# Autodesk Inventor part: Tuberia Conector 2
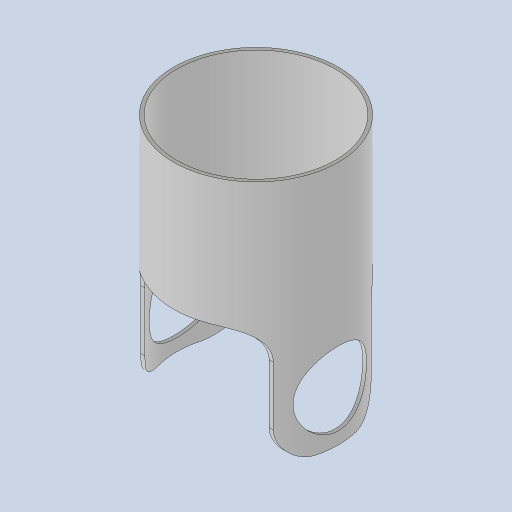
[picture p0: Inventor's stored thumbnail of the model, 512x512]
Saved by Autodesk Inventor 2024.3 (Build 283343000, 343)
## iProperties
Created: 2025-10
Part Number: Tuberia Conector 2
Material: Genérico
Document SubType Name: Modeling
Designer: Asus
Density: 1 g/cm^3
Appearance: Valor por defecto
Author: Asus
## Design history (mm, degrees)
sketch "Boceto1"
  geometry: C1 r 84.138 at (0, 0); C2 r 80.738 at (0, 0); 1 further point
  constraints: 2 centre point, 2 coincident
  dimensions: "d0" = 168.275 diameter of C1; "d1" = 3.4 radial gap between concentric circles of C1 C2
extrude "Extrusión1" new body sketch "Boceto1" distance "d2" = 250; taper "d3" = 0 deg
sketch "Boceto2"
  geometry: L1 (-250, -80.738)-(-250, 80.738) reference; L2 (-250, 84.138)-(-250, -84.138) reference; L3 (-130, 84.138)-(-130, 50); L4 (-130, 50)-(-250, 50); L5 (-250, -50)-(-130, -50); L6 (-130, -50)-(-130, -84.138); L7 (0, 84.138)-(-250, 84.138) reference; L8 (0, -84.138)-(-250, -84.138) reference; L9 (-240, 0)-(40, 0) reference; L10 (-130, 84.138)-(-250, 84.138); L11 (-250, 84.138)-(-250, 50); L12 (-250, 50)-(-130, 50); L13 (-130, 50)-(-130, 84.138); L14 (-250, -50)-(-130, -50); L15 (-130, -50)-(-130, -84.138); L16 (-130, -84.138)-(-250, -84.138); L17 (-250, -84.138)-(-250, -50); 3 further points
  constraints: 24 end point, 5 point on line, 4 parallel, 3 perpendicular, 2 horizontal, 1 vertical
  dimensions: "d4" = 100 distance between parallel lines of L5 L4; "d5" = 50 distance between parallel lines of L9 L4 (= 0.5 x d4); "d6" = 120 distance between parallel lines of L1 L6
extrude "Extrusión2" cut sketch "Boceto2" extent not by distance; stored distance "d7" = 0; taper "d8" = 0 deg
sketch "Boceto3"
  geometry: L1 (-240, 0)-(40, 0) reference; L2 (-250, -50)-(-250, 50) reference; 2 further points
  dimensions: "d9" = 0 distance from line of L1 point (-200, 0); "d10" = 50 distance from line of point (-200, 0) L2
hole "Agujero1" sketch "Boceto3" at (-200, 0) diameter "d11" = 75; stored, may be unused: countersink angle "d15" = 90 deg, drill point angle "d17" = 118 deg; dims "d12" = 6, "d13" = 4, "d14" = 2, "d16" = 8
fillet "Empalme1" dims "d18" = 30
node "Sólido1"
